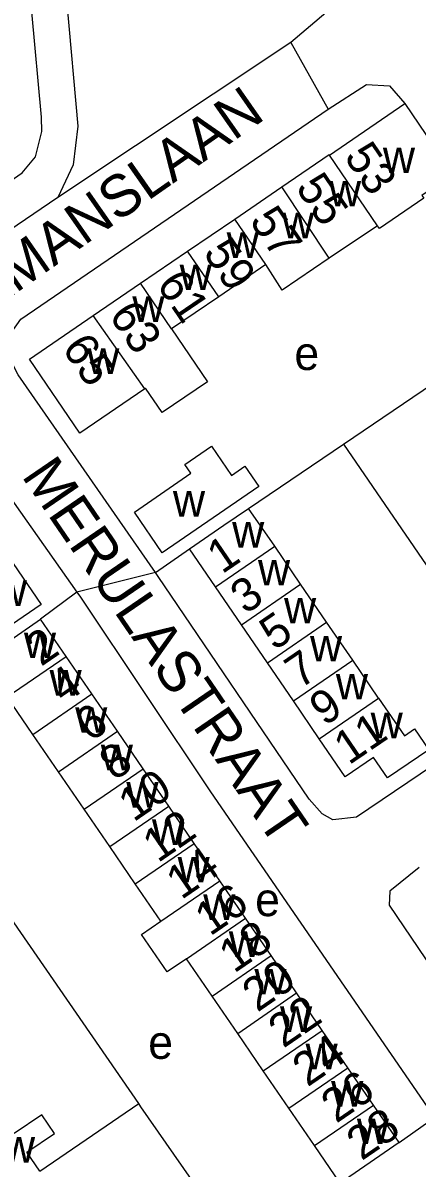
# Model space of a CAD drawing. Extents: x 157569 to 159501, y 382907 to 384670.
# Drawn here: x 158107 to 158154.4, y 383803.3 to 383940.8 of the extents above; entities that cross this region are included whole.
import ezdxf

# ---------------------------------------------------------------- set-up
doc = ezdxf.new("R2010")
doc.units = 0
for name, color, linetype in [('BLT_Basislijn', 7, 'Continuous'), ('BLT_Bebouwing', 7, 'Continuous'), ('BLT_Centroide', 7, 'Continuous'), ('BLT_Huisnummer', 7, 'Continuous'), ('BLT_Huisnummer_ tussenligend', 7, 'Continuous'), ('BLT_Onderverdeling_panden', 7, 'Continuous'), ('BLT_Straatnaam', 7, 'Continuous'), ('BLT_Vlakafsluiter', 7, 'Continuous')]:
    doc.layers.add(name, color=color, linetype=linetype)

msp = doc.modelspace()

# ---------------------------------------------------------------- linework, layer by layer
at = {"layer": 'BLT_Basislijn'}
for p, q in [((158145.59, 383890.27), (158157.67, 383898.46)), ((158101.04, 383890.18), (158113.54, 383872.48)), ((158134.18, 383882.54), (158145.59, 383890.27)), ((158145.59, 383890.27), (158167.01, 383858.88)), ((158122.98, 383874.82), (158127.07, 383877.68)), ((158113.54, 383872.48), (158109.18, 383869.24)), ((158120.99, 383811.05), (158089.92, 383855.88)), ((158109.08, 383802.96), (158120.99, 383811.05)), ((158152.26, 383806.38), (158156.52, 383809.38))]:
    msp.add_line(p, q, dxfattribs=at)
for points in [[(158050, 383884.25), (158091.59, 383912.18), (158106.97, 383922.84), (158108.56, 383924.76), (158109.31, 383927.82), (158109.28, 383929.54), (158104.65, 383980.15), (158104.61, 383984.27), (158104.87, 383985.02), (158106.49, 383988.23), (158108.15, 383989.79), (158155.97, 384027.52)], [(158159.5, 384024.29), (158110.7, 383985.62), (158109.55, 383982.64), (158109.66, 383980.15), (158112.33, 383943.19), (158113.67, 383928.45), (158113.11, 383923.79), (158111.25, 383919.87)], [(158160.76, 384019.15), (158127.95, 383992.83), (158123.48, 383987.88), (158121.69, 383982.48), (158121.85, 383977.99), (158122.65, 383975.13), (158125.88, 383969.48), (158143.06, 383945.06), (158143.48, 383943.7), (158143.46, 383942.05), (158139.23, 383938.49)], [(158139.23, 383938.49), (158111.25, 383919.87)], [(158143.74, 383930.49), (158148.33, 383933.45), (158151.12, 383933.27), (158152.94, 383931.15)], [(158122.98, 383874.82), (158106.49, 383898.56), (158105.29, 383900.94), (158105.16, 383902.94), (158106.81, 383905.27), (158143.74, 383930.49)], [(158111.25, 383919.87), (158043.67, 383873.96), (158041.62, 383871.36)], [(158167.01, 383858.88), (158147.15, 383845.47), (158144.28, 383845.12), (158143, 383845.84), (158141.46, 383847.63), (158123.32, 383874.34), (158122.98, 383874.82)], [(158113.54, 383872.48), (158113.96, 383871.88), (158129.6, 383848.51), (158156.52, 383809.38)], [(158154.66, 383839.43), (158151.16, 383836.58), (158151.07, 383834.9), (158180.71, 383791.15)], [(158133.41, 383793.23), (158121.24, 383810.68), (158120.99, 383811.05)]]:
    msp.add_lwpolyline(points, dxfattribs=at)
at = {"layer": 'BLT_Bebouwing'}
for p, q in [((158152.94, 383931.15), (158157.15, 383924.97)), ((158138.18, 383921.16), (158143.84, 383925.02)), ((158132.51, 383917.29), (158138.18, 383921.16)), ((158126.84, 383913.43), (158132.51, 383917.29)), ((158149.66, 383916.48), (158143.84, 383912.58)), ((158121.18, 383909.57), (158126.84, 383913.43)), ((158136.24, 383911.81), (158130.58, 383907.95)), ((158115.51, 383905.7), (158121.18, 383909.57)), ((158130.58, 383907.95), (158124.91, 383904.09)), ((158137.31, 383877.99), (158134.18, 383882.54)), ((158130.19, 383873.12), (158127.07, 383877.68)), ((158140.43, 383873.43), (158137.31, 383877.99)), ((158105.87, 383875.92), (158109.24, 383871)), ((158133.31, 383868.56), (158130.19, 383873.12)), ((158143.55, 383868.87), (158140.43, 383873.43)), ((158109.24, 383871), (158104.25, 383867.58)), ((158112.26, 383864.75), (158109.18, 383869.24)), ((158136.43, 383864), (158133.31, 383868.56)), ((158146.68, 383864.31), (158143.55, 383868.87)), ((158115.34, 383860.26), (158112.26, 383864.75)), ((158139.55, 383859.44), (158136.43, 383864)), ((158149.8, 383859.75), (158146.68, 383864.31)), ((158118.41, 383855.77), (158115.34, 383860.26)), ((158108.25, 383855.4), (158105.17, 383859.89)), ((158142.66, 383854.87), (158139.55, 383859.44)), ((158111.32, 383850.91), (158108.25, 383855.4)), ((158121.49, 383851.28), (158118.41, 383855.77)), ((158114.4, 383846.42), (158111.32, 383850.91)), ((158124.57, 383846.79), (158121.49, 383851.28)), ((158127.64, 383842.3), (158124.57, 383846.79)), ((158117.48, 383841.93), (158114.4, 383846.42)), ((158120.55, 383837.44), (158117.48, 383841.93)), ((158130.72, 383837.81), (158127.64, 383842.3)), ((158123.63, 383832.95), (158120.55, 383837.44)), ((158133.8, 383833.32), (158130.72, 383837.81)), ((158136.88, 383828.83), (158133.8, 383833.32)), ((158139.95, 383824.34), (158136.88, 383828.83)), ((158129.78, 383823.97), (158126.71, 383828.46)), ((158143.03, 383819.85), (158139.95, 383824.34)), ((158135.94, 383814.99), (158132.86, 383819.48)), ((158146.11, 383815.36), (158143.03, 383819.85)), ((158139.02, 383810.5), (158135.94, 383814.99)), ((158149.18, 383810.87), (158146.11, 383815.36)), ((158152.26, 383806.38), (158149.18, 383810.87)), ((158142.09, 383806.01), (158139.02, 383810.5)), ((158145.17, 383801.52), (158142.09, 383806.01))]:
    msp.add_line(p, q, dxfattribs=at)
for points in [[(158143.88, 383924.97), (158152.94, 383931.15)], [(158158.73, 383922.66), (158155, 383920.12), (158155.23, 383919.79), (158149.9, 383916.16), (158149.66, 383916.48)], [(158143.84, 383912.58), (158138.21, 383908.74), (158136.24, 383911.81)], [(158121.69, 383896.89), (158113.9, 383891.57), (158107.83, 383900.47), (158115.51, 383905.7)], [(158124.91, 383904.09), (158129.24, 383897.75), (158123.79, 383894.04), (158121.8, 383896.96), (158121.69, 383896.89)], [(158127.07, 383877.68), (158131.2, 383880.51), (158134.18, 383882.54)], [(158102.09, 383864.38), (158105.06, 383866.41), (158109.18, 383869.24)], [(158149.8, 383859.75), (158152.89, 383855.23), (158154.12, 383856.07), (158155.84, 383853.56), (158150.86, 383850.16), (158149.19, 383852.62), (158145.78, 383850.31), (158142.66, 383854.87)], [(158126.71, 383828.46), (158124.39, 383826.87), (158121.31, 383831.37), (158123.63, 383832.95)], [(158132.86, 383819.48), (158129.78, 383823.97)], [(158109.08, 383802.96), (158107.53, 383805.23), (158110.83, 383807.48), (158109.31, 383809.7), (158106.01, 383807.45)], [(158152.26, 383806.38), (158148.14, 383803.55), (158145.17, 383801.52)]]:
    msp.add_lwpolyline(points, dxfattribs=at)
msp.add_lwpolyline([(158120.45, 383882.1), (158127.24, 383886.75), (158126.52, 383887.82), (158129.72, 383890), (158132.12, 383886.48), (158133.74, 383887.59), (158135.4, 383885.16), (158123.8, 383877.21)], close=True, dxfattribs=at)
at = {"layer": 'BLT_Onderverdeling_panden'}
for p, q in [((158143.88, 383924.97), (158143.84, 383925.02)), ((158149.66, 383916.48), (158143.88, 383924.97)), ((158143.84, 383912.58), (158138.18, 383921.16)), ((158136.24, 383911.81), (158132.51, 383917.29)), ((158130.58, 383907.95), (158126.84, 383913.43)), ((158124.91, 383904.09), (158121.18, 383909.57)), ((158121.69, 383896.89), (158115.51, 383905.7)), ((158130.19, 383873.12), (158137.31, 383877.99)), ((158133.31, 383868.56), (158140.43, 383873.43)), ((158136.43, 383864), (158143.55, 383868.87)), ((158105.17, 383859.89), (158112.26, 383864.75)), ((158139.55, 383859.44), (158146.68, 383864.31)), ((158108.25, 383855.4), (158115.34, 383860.26)), ((158142.66, 383854.87), (158149.8, 383859.75)), ((158111.32, 383850.91), (158118.41, 383855.77)), ((158114.4, 383846.42), (158121.49, 383851.28)), ((158117.48, 383841.93), (158124.57, 383846.79)), ((158120.55, 383837.44), (158127.64, 383842.3)), ((158123.63, 383832.95), (158130.72, 383837.81)), ((158126.71, 383828.46), (158133.8, 383833.32)), ((158129.78, 383823.97), (158136.88, 383828.83)), ((158132.86, 383819.48), (158139.95, 383824.34)), ((158135.94, 383814.99), (158143.03, 383819.85)), ((158139.02, 383810.5), (158146.11, 383815.36)), ((158142.09, 383806.01), (158149.18, 383810.87))]:
    msp.add_line(p, q, dxfattribs=at)
at = {"layer": 'BLT_Vlakafsluiter'}
for p, q in [((158139.23, 383938.49), (158143.74, 383930.49)), ((158122.98, 383874.82), (158113.54, 383872.48))]:
    msp.add_line(p, q, dxfattribs=at)

# ---------------------------------------------------------------- texts
at = {"layer": 'BLT_Centroide'}
for s, p in [('w', (158150.31, 383922.8)), ('w', (158143.83, 383918.8)), ('w', (158138.17, 383914.97)), ('w', (158131.54, 383912.62)), ('w', (158125.88, 383908.75)), ('w', (158120.2, 383904.94)), ('w', (158114.77, 383898.67)), ('e', (158139.68, 383899.16)), ('w', (158125.08, 383881.55)), ('w', (158132.19, 383877.84)), ('w', (158135.3, 383873.28)), ('w', (158103.68, 383870.83)), ('w', (158138.43, 383868.72)), ('w', (158107.17, 383864.56)), ('w', (158141.55, 383864.16)), ('w', (158110.25, 383860.06)), ('w', (158144.66, 383859.59)), ('w', (158113.33, 383855.59)), ('w', (158148.84, 383854.94)), ('w', (158116.41, 383851.09)), ('w', (158119.48, 383846.59)), ('w', (158122.56, 383842.12)), ('w', (158125.64, 383837.62)), ('w', (158128.72, 383833.12)), ('e', (158134.96, 383833.57)), ('w', (158131.8, 383828.66)), ('w', (158134.87, 383824.16)), ('w', (158137.95, 383819.66)), ('e', (158122.11, 383816.43)), ('w', (158141.02, 383815.19)), ('w', (158144.09, 383810.69)), ('w', (158147.18, 383806.19)), ('w', (158104.65, 383803.97))]:
    msp.add_text(s, height=4, dxfattribs=at).set_placement(p)
at = {"layer": 'BLT_Huisnummer'}
for s, rotation, p in [('53', 304.282, (158145.56, 383924.76)), ('57', 304.2797, (158134.19, 383917.07)), ('61', 304.2797, (158123.02, 383909.42)), ('65', 304.2846, (158111.66, 383901.77)), ('1', 34.3471, (158130.98, 383874.59)), ('5', 34.3471, (158137.29, 383865.39)), ('2', 34.4206, (158109.23, 383863.49)), ('6', 34.4206, (158115.13, 383854.4)), ('11', 34.1955, (158146.22, 383851.65)), ('10', 34.4206, (158120.34, 383844.8)), ('14', 34.4206, (158126.08, 383835.47)), ('18', 34.4206, (158132.42, 383826.64)), ('22', 34.4206, (158138.35, 383817.64)), ('28', 34.4206, (158147.75, 383804.13))]:
    msp.add_text(s, height=4, rotation=rotation, dxfattribs=at).set_placement(p)
at = {"layer": 'BLT_Huisnummer_ tussenligend'}
for s, rotation, p in [('55', 304.282, (158139.74, 383921.05)), ('59', 304.2797, (158128.63, 383913.23)), ('63', 304.2797, (158117.3, 383905.7)), ('3', 34.3471, (158133.79, 383869.74)), ('7', 34.3471, (158140.34, 383860.78)), ('4', 34.4206, (158112, 383858.98)), ('9', 34.3471, (158143.3, 383856.31)), ('8', 34.4206, (158118.05, 383849.76)), ('12', 34.4206, (158123.26, 383839.9)), ('16', 34.4206, (158129.53, 383831.09)), ('20', 34.4206, (158135.22, 383821.96)), ('24', 34.4206, (158141.25, 383812.99)), ('26', 34.4206, (158144.7, 383808.62))]:
    msp.add_text(s, height=4, rotation=rotation, dxfattribs=at).set_placement(p)
at = {"layer": 'BLT_Straatnaam'}
for s, height, rotation, p in [('PIETER STOCKMANSLAAN', 5, 34.9363, (158065.98, 383880.24)), ('MERULASTRAAT', 4.9999, 304.3715, (158106.8, 383886.44)), ('SIMON VAN LEEUWENSTRAAT', 5, 304.683, (158053.35, 383847.75))]:
    msp.add_text(s, height=height, rotation=rotation, dxfattribs=at).set_placement(p)

doc.saveas('drawing.dxf')
